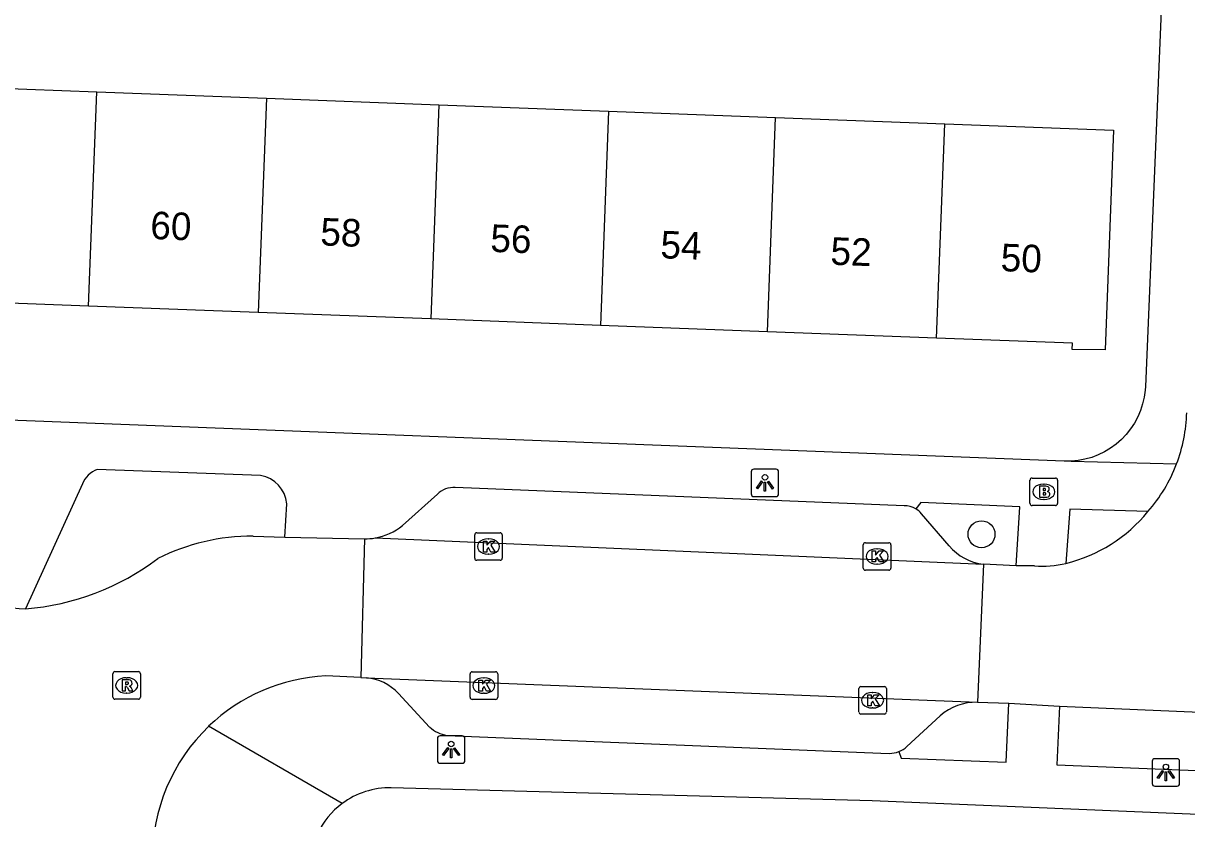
# Model space of a CAD drawing. Extents: x 161355 to 162026, y 386504 to 387459.
# Drawn here: x 161519.49 to 161561.75, y 387285.02 to 387313.91 of the extents above; entities that cross this region are included whole.
import ezdxf

# ---------------------------------------------------------------- set-up
doc = ezdxf.new("R2010")
doc.units = 0
for name, color, linetype in [('IMGEO_Boom', 7, 'Continuous'), ('IMGEO_Brandkraan', 7, 'Continuous'), ('IMGEO_Kolk', 7, 'Continuous'), ('IMGEO_Lichtpunt', 7, 'Continuous'), ('IMGEO_Pand', 7, 'Continuous'), ('IMGEO_Pand_nummerreeks', 7, 'Continuous'), ('IMGEO_Parkeervlak_open', 7, 'Continuous'), ('IMGEO_Rijbaan_lokaal_open', 7, 'Continuous'), ('IMGEO_Rioolput', 7, 'Continuous'), ('IMGEO_Voetpad_open', 7, 'Continuous')]:
    doc.layers.add(name, color=color, linetype=linetype)

msp = doc.modelspace()

# ---------------------------------------------------------------- linework, layer by layer
at = {"layer": 'IMGEO_Boom'}
msp.add_circle((161554.3, 387295.355), 0.489, dxfattribs=at)
at = {"layer": 'IMGEO_Brandkraan'}
for p, q in [((161556.136, 387297.396), (161556.988, 387297.396)), ((161556.061, 387296.47), (161556.061, 387297.322)), ((161556.549, 387297.176), (161556.574, 387297.176)), ((161557.062, 387297.322), (161557.062, 387296.47)), ((161556.572, 387296.616), (161556.547, 387296.616)), ((161556.988, 387296.396), (161556.136, 387296.396))]:
    msp.add_line(p, q, dxfattribs=at)
for points in [[(161556.136, 387297.396), (161556.988, 387297.396)], [(161556.061, 387296.47), (161556.061, 387297.322)], [(161556.409, 387297.096), (161556.409, 387296.696), (161556.622, 387296.696)], [(161556.64, 387297.096), (161556.409, 387297.096)], [(161556.588, 387297.015), (161556.534, 387297.015), (161556.534, 387296.939)], [(161556.534, 387296.939), (161556.587, 387296.939)], [(161557.062, 387297.322), (161557.062, 387296.47)], [(161556.596, 387296.863), (161556.534, 387296.863), (161556.534, 387296.782)], [(161556.534, 387296.782), (161556.596, 387296.782)], [(161556.988, 387296.396), (161556.136, 387296.396)]]:
    msp.add_lwpolyline(points, dxfattribs=at)
for centre, radius, start, end in [((161556.138, 387297.32), 0.0765, 91.552, 178.448), ((161556.138, 387297.32), 0.0765, 91.552, 178.448), ((161556.986, 387297.32), 0.0765, 1.552, 88.448), ((161556.986, 387297.32), 0.0765, 1.552, 88.448), ((161556.589, 387296.977), 0.0379, 267.8285, 90.9355), ((161556.644, 387296.951), 0.145, 59.4692, 91.5367), ((161556.669, 387296.998), 0.0922, 285.5137, 58.1501), ((161556.674, 387296.806), 0.105, 301.3115, 78.989), ((161556.597, 387296.822), 0.0404, 269.8759, 90.5077), ((161556.628, 387296.947), 0.251, 268.6676, 293.5347), ((161556.138, 387296.472), 0.0765, 181.552, 268.448), ((161556.138, 387296.472), 0.0765, 181.552, 268.448), ((161556.986, 387296.472), 0.0765, 271.552, 358.448), ((161556.986, 387296.472), 0.0765, 271.552, 358.448)]:
    msp.add_arc(centre, radius, start, end, dxfattribs=at)
for centre, major_axis, ratio, start_param, end_param in [((161556.548, 387296.896), (-0.387, 0.002), 0.722429, 4.712389, 7.853982), ((161556.573, 387296.896), (-0.39, 0.002), 0.717154, 1.570796, 4.712389)]:
    msp.add_ellipse(centre, major_axis=major_axis, ratio=ratio, start_param=start_param, end_param=end_param, dxfattribs=at)
at = {"layer": 'IMGEO_Kolk'}
for p, q in [((161535.89, 387294.481), (161535.89, 387295.333)), ((161535.965, 387295.407), (161536.817, 387295.407)), ((161536.891, 387295.333), (161536.891, 387294.481)), ((161536.378, 387295.187), (161536.403, 387295.187)), ((161550.006, 387294.121), (161550.006, 387294.973)), ((161550.081, 387295.047), (161550.933, 387295.047)), ((161550.494, 387294.827), (161550.519, 387294.827)), ((161551.007, 387294.973), (161551.007, 387294.121)), ((161536.817, 387294.407), (161535.965, 387294.407)), ((161536.401, 387294.627), (161536.376, 387294.627)), ((161550.933, 387294.047), (161550.081, 387294.047)), ((161550.517, 387294.267), (161550.492, 387294.267)), ((161535.725, 387289.43), (161535.725, 387290.282)), ((161535.8, 387290.356), (161536.652, 387290.356)), ((161536.726, 387290.282), (161536.726, 387289.43)), ((161536.213, 387290.136), (161536.238, 387290.136)), ((161549.844, 387288.897), (161549.844, 387289.749)), ((161549.919, 387289.823), (161550.771, 387289.823)), ((161550.845, 387289.749), (161550.845, 387288.897)), ((161536.652, 387289.356), (161535.8, 387289.356)), ((161536.236, 387289.576), (161536.211, 387289.576)), ((161550.332, 387289.603), (161550.357, 387289.603)), ((161550.355, 387289.043), (161550.33, 387289.043)), ((161550.771, 387288.823), (161549.919, 387288.823))]:
    msp.add_line(p, q, dxfattribs=at)
for points in [[(161535.89, 387294.481), (161535.89, 387295.333)], [(161535.965, 387295.407), (161536.817, 387295.407)], [(161536.891, 387295.333), (161536.891, 387294.481)], [(161536.211, 387295.107), (161536.334, 387295.107), (161536.334, 387294.956), (161536.464, 387295.107), (161536.628, 387295.107), (161536.482, 387294.956), (161536.635, 387294.707), (161536.483, 387294.707), (161536.398, 387294.871), (161536.334, 387294.804), (161536.334, 387294.707), (161536.211, 387294.707), (161536.211, 387295.107)], [(161550.006, 387294.121), (161550.006, 387294.973)], [(161550.081, 387295.047), (161550.933, 387295.047)], [(161551.007, 387294.973), (161551.007, 387294.121)], [(161536.817, 387294.407), (161535.965, 387294.407)], [(161550.327, 387294.747), (161550.45, 387294.747), (161550.45, 387294.596), (161550.58, 387294.747), (161550.744, 387294.747), (161550.598, 387294.596), (161550.751, 387294.347), (161550.599, 387294.347), (161550.514, 387294.511), (161550.45, 387294.444), (161550.45, 387294.347), (161550.327, 387294.347), (161550.327, 387294.747)], [(161550.933, 387294.047), (161550.081, 387294.047)], [(161535.725, 387289.43), (161535.725, 387290.282)], [(161535.8, 387290.356), (161536.652, 387290.356)], [(161536.726, 387290.282), (161536.726, 387289.43)], [(161536.046, 387290.056), (161536.169, 387290.056), (161536.169, 387289.905), (161536.299, 387290.056), (161536.463, 387290.056), (161536.317, 387289.905), (161536.47, 387289.656), (161536.318, 387289.656), (161536.233, 387289.82), (161536.169, 387289.753), (161536.169, 387289.656), (161536.046, 387289.656), (161536.046, 387290.056)], [(161549.844, 387288.897), (161549.844, 387289.749)], [(161549.919, 387289.823), (161550.771, 387289.823)], [(161550.845, 387289.749), (161550.845, 387288.897)], [(161536.652, 387289.356), (161535.8, 387289.356)], [(161550.165, 387289.523), (161550.288, 387289.523), (161550.288, 387289.372), (161550.418, 387289.523), (161550.582, 387289.523), (161550.436, 387289.372), (161550.589, 387289.123), (161550.437, 387289.123), (161550.352, 387289.287), (161550.288, 387289.22), (161550.288, 387289.123), (161550.165, 387289.123), (161550.165, 387289.523)], [(161550.771, 387288.823), (161549.919, 387288.823)]]:
    msp.add_lwpolyline(points, dxfattribs=at)
for centre, start, end in [((161535.967, 387295.331), 91.552, 178.448), ((161535.967, 387295.331), 91.552, 178.448), ((161536.815, 387295.331), 1.552, 88.448), ((161536.815, 387295.331), 1.552, 88.448), ((161550.083, 387294.971), 91.552, 178.448), ((161550.083, 387294.971), 91.552, 178.448), ((161550.931, 387294.971), 1.552, 88.448), ((161550.931, 387294.971), 1.552, 88.448), ((161535.967, 387294.483), 181.552, 268.448), ((161535.967, 387294.483), 181.552, 268.448), ((161536.815, 387294.483), 271.552, 358.448), ((161536.815, 387294.483), 271.552, 358.448), ((161550.083, 387294.123), 181.552, 268.448), ((161550.083, 387294.123), 181.552, 268.448), ((161550.931, 387294.123), 271.552, 358.448), ((161550.931, 387294.123), 271.552, 358.448), ((161535.802, 387290.28), 91.552, 178.448), ((161535.802, 387290.28), 91.552, 178.448), ((161536.65, 387290.28), 1.552, 88.448), ((161536.65, 387290.28), 1.552, 88.448), ((161549.921, 387289.747), 91.552, 178.448), ((161549.921, 387289.747), 91.552, 178.448), ((161550.769, 387289.747), 1.552, 88.448), ((161550.769, 387289.747), 1.552, 88.448), ((161535.802, 387289.432), 181.552, 268.448), ((161535.802, 387289.432), 181.552, 268.448), ((161536.65, 387289.432), 271.552, 358.448), ((161536.65, 387289.432), 271.552, 358.448), ((161549.921, 387288.899), 181.552, 268.448), ((161549.921, 387288.899), 181.552, 268.448), ((161550.769, 387288.899), 271.552, 358.448), ((161550.769, 387288.899), 271.552, 358.448)]:
    msp.add_arc(centre, 0.0765, start, end, dxfattribs=at)
for centre, major_axis, ratio, start_param, end_param in [((161536.377, 387294.907), (-0.387, 0.002), 0.722429, 4.712389, 7.853982), ((161536.402, 387294.907), (-0.39, 0.002), 0.717154, 1.570796, 4.712389), ((161550.493, 387294.547), (-0.387, 0.002), 0.722429, 4.712389, 7.853982), ((161550.518, 387294.547), (-0.39, 0.002), 0.717154, 1.570796, 4.712389), ((161536.212, 387289.856), (-0.387, 0.002), 0.722429, 4.712389, 7.853982), ((161536.237, 387289.856), (-0.39, 0.002), 0.717154, 1.570796, 4.712389), ((161550.331, 387289.323), (-0.387, 0.002), 0.722429, 4.712389, 7.853982), ((161550.356, 387289.323), (-0.39, 0.002), 0.717154, 1.570796, 4.712389)]:
    msp.add_ellipse(centre, major_axis=major_axis, ratio=ratio, start_param=start_param, end_param=end_param, dxfattribs=at)
at = {"layer": 'IMGEO_Lichtpunt'}
for p, q in [((161545.935, 387297.624), (161545.935, 387296.817)), ((161545.935, 387297.624), (161545.935, 387296.817)), ((161546.837, 387297.719), (161546.029, 387297.719)), ((161546.837, 387297.719), (161546.029, 387297.719)), ((161546.931, 387296.817), (161546.931, 387297.624)), ((161546.931, 387296.817), (161546.931, 387297.624)), ((161546.029, 387296.723), (161546.837, 387296.723)), ((161546.029, 387296.723), (161546.837, 387296.723)), ((161535.44, 387288.033), (161534.632, 387288.033)), ((161535.44, 387288.033), (161534.632, 387288.033)), ((161534.538, 387287.938), (161534.538, 387287.131)), ((161534.538, 387287.938), (161534.538, 387287.131)), ((161535.534, 387287.131), (161535.534, 387287.938)), ((161535.534, 387287.131), (161535.534, 387287.938)), ((161561.401, 387287.201), (161560.593, 387287.201)), ((161561.401, 387287.201), (161560.593, 387287.201)), ((161534.632, 387287.037), (161535.44, 387287.037)), ((161534.632, 387287.037), (161535.44, 387287.037)), ((161560.499, 387287.106), (161560.499, 387286.299)), ((161560.499, 387287.106), (161560.499, 387286.299)), ((161561.495, 387286.299), (161561.495, 387287.106)), ((161561.495, 387286.299), (161561.495, 387287.106)), ((161560.593, 387286.205), (161561.401, 387286.205)), ((161560.593, 387286.205), (161561.401, 387286.205))]:
    msp.add_line(p, q, dxfattribs=at)
for points in [[(161546.309, 387297.288), (161546.348, 387297.26), (161546.16, 387296.998), (161546.122, 387297.025), (161546.309, 387297.288)], [(161546.411, 387297.24), (161546.458, 387297.24), (161546.458, 387296.918), (161546.411, 387296.918), (161546.411, 387297.24)], [(161546.521, 387297.26), (161546.559, 387297.287), (161546.746, 387297.025), (161546.707, 387296.997), (161546.521, 387297.26)], [(161534.912, 387287.602), (161534.951, 387287.574), (161534.763, 387287.312), (161534.725, 387287.339), (161534.912, 387287.602)], [(161535.014, 387287.554), (161535.061, 387287.554), (161535.061, 387287.232), (161535.014, 387287.232), (161535.014, 387287.554)], [(161535.124, 387287.574), (161535.162, 387287.601), (161535.349, 387287.339), (161535.31, 387287.311), (161535.124, 387287.574)], [(161560.873, 387286.77), (161560.912, 387286.742), (161560.724, 387286.48), (161560.686, 387286.507), (161560.873, 387286.77)], [(161561.085, 387286.742), (161561.123, 387286.769), (161561.31, 387286.507), (161561.271, 387286.479), (161561.085, 387286.742)], [(161560.975, 387286.722), (161561.022, 387286.722), (161561.022, 387286.4), (161560.975, 387286.4), (161560.975, 387286.722)]]:
    msp.add_lwpolyline(points, dxfattribs=at)
for centre in [(161546.434, 387297.422), (161535.037, 387287.736), (161560.998, 387286.904)]:
    msp.add_circle(centre, 0.0994, dxfattribs=at)
for centre, start, end in [((161546.029, 387297.624), 90, 180), ((161546.029, 387297.624), 90, 180), ((161546.837, 387297.624), 0, 90), ((161546.837, 387297.624), 0, 90), ((161546.029, 387296.817), 180, 270), ((161546.029, 387296.817), 180, 270), ((161546.837, 387296.817), 270, 0), ((161546.837, 387296.817), 270, 360), ((161534.632, 387287.938), 90, 180), ((161534.632, 387287.938), 90, 180), ((161535.44, 387287.938), 0, 90), ((161535.44, 387287.938), 0, 90), ((161560.593, 387287.106), 90, 180), ((161560.593, 387287.106), 90, 180), ((161561.401, 387287.106), 0, 90), ((161561.401, 387287.106), 0, 90), ((161534.632, 387287.131), 180, 270), ((161534.632, 387287.131), 180, 270), ((161535.44, 387287.131), 270, 0), ((161535.44, 387287.131), 270, 360), ((161560.593, 387286.299), 180, 270), ((161560.593, 387286.299), 180, 270), ((161561.401, 387286.299), 270, 0), ((161561.401, 387286.299), 270, 360)]:
    msp.add_arc(centre, 0.0946, start, end, dxfattribs=at)
at = {"layer": 'IMGEO_Pand'}
for points in [[(161515.799, 387311.663), (161522.162, 387311.424)], [(161521.869, 387303.644), (161522.162, 387311.424)], [(161522.162, 387311.424), (161528.323, 387311.192)], [(161528.323, 387311.192), (161528.03, 387303.411)], [(161528.323, 387311.192), (161534.592, 387310.957)], [(161534.592, 387310.957), (161534.299, 387303.173)], [(161534.592, 387310.957), (161540.752, 387310.725)], [(161540.752, 387310.725), (161540.459, 387302.94)], [(161540.752, 387310.725), (161546.814, 387310.497)], [(161546.521, 387302.711), (161546.814, 387310.497)], [(161546.814, 387310.497), (161552.962, 387310.266)], [(161552.962, 387310.266), (161559.093, 387310.036), (161558.793, 387302.047), (161557.587, 387302.068), (161557.599, 387302.292), (161552.669, 387302.479)], [(161552.669, 387302.479), (161552.962, 387310.266)], [(161521.869, 387303.644), (161515.506, 387303.884)], [(161528.03, 387303.411), (161521.869, 387303.644)], [(161534.299, 387303.173), (161528.03, 387303.411)], [(161540.459, 387302.94), (161534.299, 387303.173)], [(161546.521, 387302.711), (161540.459, 387302.94)], [(161552.669, 387302.479), (161546.521, 387302.711)]]:
    msp.add_lwpolyline(points, dxfattribs=at)
at = {"layer": 'IMGEO_Parkeervlak_open'}
for points in [[(161553.128, 387294.935), (161552.116, 387296.1)], [(161552.795, 387288.757), (161551.591, 387287.64)]]:
    msp.add_lwpolyline(points, dxfattribs=at)
for centre, radius, start, end in [((161551.54, 387295.647), 0.733, 38.1705, 59.5764), ((161554.592, 387296.165), 1.912, 220.0292, 263.2756), ((161554.121, 387287.231), 2.022, 89.1364, 130.9723), ((161550.954, 387288.345), 0.95, 291.3674, 312.1108)]:
    msp.add_arc(centre, radius, start, end, dxfattribs=at)
at = {"layer": 'IMGEO_Rijbaan_lokaal_open'}
for points in [[(161527.844, 387295.285), (161528.989, 387295.252)], [(161528.989, 387295.252), (161531.889, 387295.186)], [(161532.273, 387295.218), (161554.368, 387294.266)], [(161531.889, 387295.186), (161531.758, 387290.15)], [(161554.368, 387294.266), (161554.151, 387289.252)], [(161555.56, 387294.201), (161554.368, 387294.266)], [(161556.22, 387294.202), (161555.56, 387294.201)], [(161531.758, 387290.15), (161530.484, 387290.205)], [(161531.758, 387290.15), (161531.958, 387290.142)], [(161531.958, 387290.142), (161554.151, 387289.252)], [(161554.151, 387289.252), (161555.294, 387289.212)], [(161555.294, 387289.212), (161557.129, 387289.105)], [(161557.129, 387289.105), (161569.317, 387288.584)]]:
    msp.add_lwpolyline(points, dxfattribs=at)
for centre, radius, start, end in [((161556.046, 387299.935), 5.71, 339.1937, 358.3403), ((161556.045, 387299.937), 5.712, 318.8204, 339.1839), ((161556.028, 387299.706), 5.576, 283.8748, 320.7185), ((161527.808, 387287.623), 7.662, 89.7306, 116.5845), ((161531.89, 387297.494), 2.308, 269.9753, 279.552), ((161518.878, 387301.71), 9.089, 274.3974, 307.247), ((161556.488, 387298.078), 3.885, 266.0441, 283.0441), ((161519.847, 387300.392), 7.749, 254.336, 267.9872), ((161530.801, 387283.595), 6.618, 92.7497, 133.7157), ((161530.805, 387283.597), 6.618, 133.7511, 180.7637)]:
    msp.add_arc(centre, radius, start, end, dxfattribs=at)
at = {"layer": 'IMGEO_Rioolput'}
for p, q in [((161522.749, 387289.437), (161522.749, 387290.289)), ((161522.824, 387290.363), (161523.676, 387290.363)), ((161523.75, 387290.289), (161523.75, 387289.437)), ((161523.237, 387290.143), (161523.262, 387290.143)), ((161523.676, 387289.363), (161522.824, 387289.363)), ((161523.26, 387289.583), (161523.235, 387289.583))]:
    msp.add_line(p, q, dxfattribs=at)
for points in [[(161522.749, 387289.437), (161522.749, 387290.289)], [(161522.824, 387290.363), (161523.676, 387290.363)], [(161523.75, 387290.289), (161523.75, 387289.437)], [(161523.338, 387290.061), (161523.086, 387290.063), (161523.086, 387289.663)], [(161523.086, 387289.663), (161523.21, 387289.663), (161523.21, 387289.825), (161523.221, 387289.825)], [(161523.264, 387289.982), (161523.21, 387289.982), (161523.21, 387289.901)], [(161523.21, 387289.901), (161523.262, 387289.901)], [(161523.268, 387289.796), (161523.339, 387289.663), (161523.479, 387289.663), (161523.414, 387289.789)], [(161523.676, 387289.363), (161522.824, 387289.363)]]:
    msp.add_lwpolyline(points, dxfattribs=at)
for centre, radius, start, end in [((161522.826, 387290.287), 0.0765, 91.552, 178.448), ((161522.826, 387290.287), 0.0765, 91.552, 178.448), ((161523.674, 387290.287), 0.0765, 1.552, 88.448), ((161523.674, 387290.287), 0.0765, 1.552, 88.448), ((161523.22, 387289.772), 0.0533, 26.0293, 88.6989), ((161523.246, 387290.09), 0.19, 274.7715, 282.9687), ((161523.27, 387289.886), 0.0964, 77.0061, 93.1865), ((161523.284, 387289.943), 0.0378, 276.6634, 79.6772), ((161523.337, 387289.951), 0.109, 350.3612, 89.416), ((161523.335, 387289.951), 0.112, 277.5842, 350.9817), ((161523.319, 387289.736), 0.108, 29.5134, 73.7905), ((161522.826, 387289.439), 0.0765, 181.552, 268.448), ((161522.826, 387289.439), 0.0765, 181.552, 268.448), ((161523.674, 387289.439), 0.0765, 271.552, 358.448), ((161523.674, 387289.439), 0.0765, 271.552, 358.448)]:
    msp.add_arc(centre, radius, start, end, dxfattribs=at)
for centre, major_axis, ratio, start_param, end_param in [((161523.236, 387289.863), (-0.387, 0.002), 0.722429, 4.712389, 7.853982), ((161523.261, 387289.863), (-0.39, 0.002), 0.717154, 1.570796, 4.712389)]:
    msp.add_ellipse(centre, major_axis=major_axis, ratio=ratio, start_param=start_param, end_param=end_param, dxfattribs=at)
at = {"layer": 'IMGEO_Voetpad_open'}
for points in [[(161561.109, 387321.064), (161560.252, 387300.722), (161560.243, 387300.587), (161560.209, 387300.336), (161560.152, 387300.088), (161560.074, 387299.847), (161559.974, 387299.613), (161559.854, 387299.39), (161559.714, 387299.178), (161559.556, 387298.979), (161559.381, 387298.796), (161559.191, 387298.628), (161558.986, 387298.479), (161558.768, 387298.348), (161558.54, 387298.237), (161558.302, 387298.147), (161558.058, 387298.079), (161557.808, 387298.033), (161557.556, 387298.009)], [(161557.556, 387298.009), (161557.302, 387298.008), (161510.562, 387299.829)], [(161557.556, 387298.009), (161561.384, 387297.907)], [(161528.115, 387297.49), (161522.181, 387297.706)], [(161521.641, 387297.183), (161519.575, 387292.648)], [(161551.496, 387296.384), (161535.185, 387297.055)], [(161534.534, 387296.814), (161533.274, 387295.671)], [(161555.56, 387294.201), (161555.69, 387296.345), (161552.09, 387296.502), (161551.911, 387296.279)], [(161528.989, 387295.252), (161529.062, 387296.461)], [(161560.344, 387296.176), (161557.511, 387296.269), (161557.365, 387294.293)], [(161533.123, 387289.572), (161534.255, 387288.351)], [(161551.3, 387287.46), (161551.382, 387287.219), (161555.198, 387287.074), (161555.294, 387289.212)], [(161557.129, 387289.105), (161557.035, 387286.982), (161569.249, 387286.485), (161569.317, 387288.584)], [(161531.075, 387285.569), (161526.228, 387288.378)], [(161534.884, 387288.049), (161550.947, 387287.395)], [(161623.949, 387282.537), (161622.786, 387282.637), (161550.326, 387285.67), (161532.862, 387286.146)]]:
    msp.add_lwpolyline(points, dxfattribs=at)
for centre, radius, start, end in [((161522.503, 387296.833), 0.93, 110.2472, 157.9204), ((161527.928, 387296.367), 1.138, 4.7261, 80.5213), ((161535.149, 387296.152), 0.903, 87.7164, 132.9127), ((161551.527, 387295.635), 0.75, 59.2098, 92.3931), ((161531.897, 387297.382), 2.196, 279.8619, 308.8361), ((161531.785, 387288.312), 1.838, 43.2703, 84.5874), ((161535.046, 387289.192), 1.154, 226.7626, 261.9435), ((161550.952, 387288.359), 0.964, 269.6989, 291.1678), ((161532.819, 387283.224), 2.922, 89.1514, 126.6378), ((161532.817, 387283.22), 2.925, 126.5671, 182.2175)]:
    msp.add_arc(centre, radius, start, end, dxfattribs=at)

# ---------------------------------------------------------------- texts
at = {"layer": 'IMGEO_Pand_nummerreeks'}
for s, p in [('60', (161524.096, 387306.082)), ('58', (161530.273, 387305.848)), ('56', (161536.448, 387305.614)), ('54', (161542.626, 387305.381)), ('52', (161548.801, 387305.147)), ('50', (161554.984, 387304.913))]:
    msp.add_text(s, height=1, rotation=357.8335, dxfattribs=at).set_placement(p)

doc.saveas('drawing.dxf')
